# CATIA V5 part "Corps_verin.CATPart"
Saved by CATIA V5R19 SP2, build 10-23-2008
Part number: Corps_verin
Bounding box of the stored display mesh (mm): x -80 to 80, y -50 to 816.271, z -150 to 79.98
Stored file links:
  C:\Users\matthieu\Desktop\IAO\modele_CAO\Corps_verin.CATPart
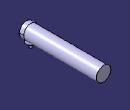
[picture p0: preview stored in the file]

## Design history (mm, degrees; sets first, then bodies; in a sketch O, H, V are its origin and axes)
Body1 (main body)
  Sketch1 on yz-plane, origin (0, 0, 0), H (0, 1, 0), V (0, 0, 1)
    point P1 (766.2711, 0)
    line L1 (766.2711, 0) -> (816.2711, 0)
    line L2 (816.2711, 0) -> (816.2711, 80)
    line L3 (816.2711, 80) -> (0, 80)
    point P4 (0, 80)
    line L4 (0, 80) -> (0, 30)
    line L5 (0, 30) -> (766.2711, 30)
    line L6 (766.2711, 30) -> (766.2711, 0)
    axis line L7 (766.2711, 0) -> (421.2025, 0)
    distance L6 L4 = 766.2711
    length L1 = 50
    distance L5 L3 = 50
    "Radius" L5 L7 = 30
    coincidence: P1 H, P4 V
    horizontal: L1 H, L3 H, L5 H, L7 H
    vertical: L2 V, L4 V, L6 V
  Shaft1: profile Sketch1, axis Sketch1.L7, angle 360
  Sketch2 on zx-plane, origin (0, 0, 0), H (-1, 0, 0), V (0, 0, 1)
    point P1 (0, -30)
    line L1 (0, -30) -> (0, -150)
    line L2 (0, -150) -> (-15, -150)
    line L3 (-15, -150) -> (-15, -100)
    line L4 (-15, -100) -> (-50, -100)
    line L5 (-50, -100) -> (-50, -30)
    line L6 (-50, -30) -> (0, -30)
    axis line L7 (0, -150) -> (0, -182.6749)
    distance L3 L1 = 15
    length L3 = 50
    distance H L4 = 100
    length L6 = 50
    distance H L6 = 30
    coincidence: P1 V
    vertical: L1 V, L3 V, L5 V, L7 V
    horizontal: L2 H, L4 H, L6 H
  Shaft2: profile Sketch2, axis Sketch2.L7, angle 360
  Sketch3 on face of Shaft1 from Sketch1.L4, origin (0, 0, 0), H (1, 0, 0), V (0, 0, 1)
    circle A1 centre (0, 0) radius 80
    circle A2 centre (0, 0) radius 30
    reference projected circle E1 centre (0, 0) radius 30 from edge [face of Shaft1 from Sketch1.L4 | face of Shaft1 from Sketch1.L5]
    reference projected circle E2 centre (0, 0) radius 80 from edge [face of Shaft1 from Sketch1.L3 | face of Shaft1 from Sketch1.L4]
    coincidence: A2 E1, A1 E2
  Pad1: profile Sketch3, direction (0, -1, 0), length 50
